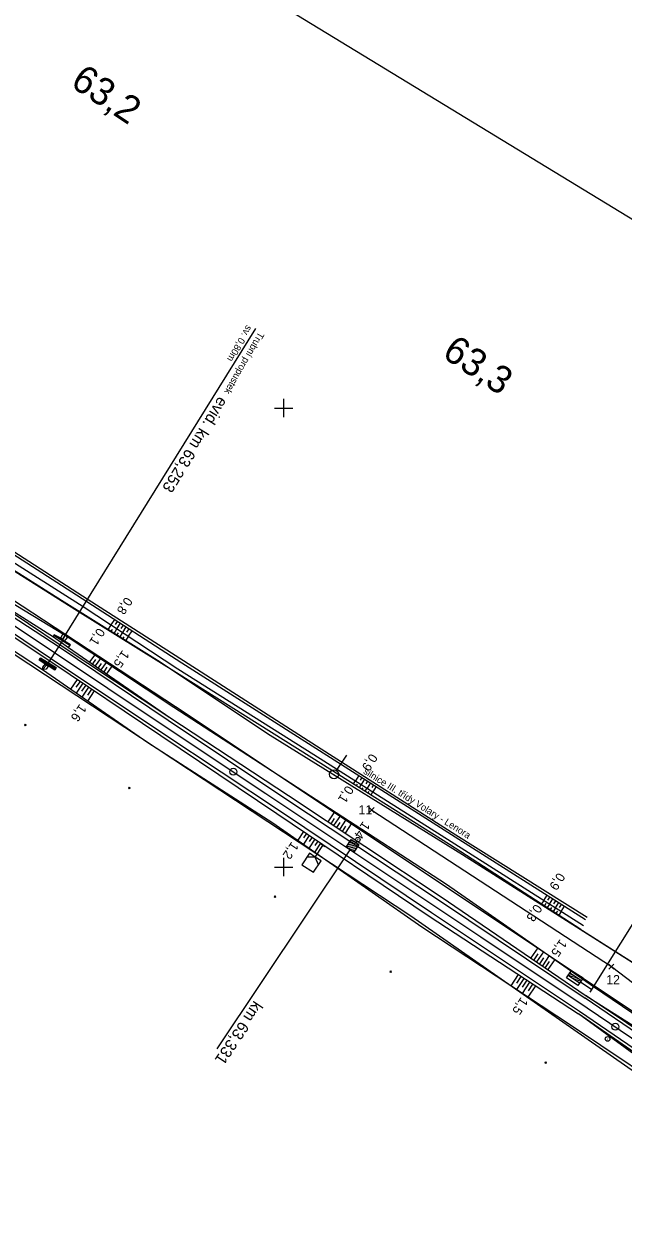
# Model space of a CAD drawing. Extents: x -804899 to -803847, y -1165742 to -1164942.
# Drawn here: x -804356.6 to -804226, y -1165474.6 to -1165216.2 of the extents above; entities that cross this region are included whole.
import ezdxf

# ---------------------------------------------------------------- set-up
doc = ezdxf.new("R2010")
doc.units = 0
for name, color, linetype in [('0381KM061-064P - Vrstva 1', 7, 'Continuous'), ('0381KM061-064P - Vrstva 13', 7, 'Continuous'), ('0381KM061-064P - Vrstva 17', 7, 'Continuous'), ('0381KM061-064P - Vrstva 19', 7, 'Continuous'), ('0381KM061-064P - Vrstva 27', 7, 'Continuous'), ('0381KM061-064P - Vrstva 3', 7, 'Continuous'), ('0381KM061-064P - Vrstva 36', 7, 'Continuous'), ('0381KM061-064P - Vrstva 4', 7, 'Continuous'), ('0381KM061-064P - Vrstva 48', 7, 'Continuous'), ('0381KM061-064P - Vrstva 49', 7, 'Continuous'), ('0381KM061-064P - Vrstva 51', 7, 'Continuous'), ('0381KM061-064P - Vrstva 55', 7, 'Continuous'), ('0381KM061-064P - Vrstva 7', 7, 'Continuous'), ('0381KM061-064P - Vrstva 8', 7, 'Continuous'), ('Default', 7, 'Continuous'), ('formát', 7, 'Continuous'), ('hran DP - hran DP', 7, 'Continuous'), ('krizky_1000 - Vrstva 1', 7, 'Continuous'), ('PSR_C2_3_Lomove_body_Lenora - Vrstva 60', 7, 'Continuous'), ('PSR_C2_3_trasa_Lenora - Kabelová trasa', 7, 'Continuous')]:
    doc.layers.add(name, color=color, linetype=linetype)

msp = doc.modelspace()

# ---------------------------------------------------------------- linework, layer by layer
at = {"layer": '0381KM061-064P - Vrstva 1'}
for points in [[(-804619.36, -1165173.74), (-804594.78, -1165190.05), (-804577, -1165201.91), (-804561.16, -1165212.47), (-804538.32, -1165227.67), (-804515.3, -1165243.02), (-804489.41, -1165260.27), (-804477.81, -1165268), (-804447.6, -1165288.14), (-804422.03, -1165305.2), (-804398.19, -1165321.09), (-804394.23, -1165323.73), (-804371.85, -1165338.65), (-804349.9, -1165353.29), (-804326.64, -1165368.8), (-804303.84, -1165384.01), (-804280.33, -1165399.7), (-804257.04, -1165415.23), (-804233.85, -1165430.69)], [(-804233.85, -1165430.69), (-804221.71, -1165438.86), (-804209.06, -1165447.77)]]:
    msp.add_lwpolyline(points, dxfattribs=at)
at = {"layer": '0381KM061-064P - Vrstva 13'}
for points in [[(-804348.53, -1165350.16), (-804348.11, -1165349.19), (-804347.55, -1165349.48)], [(-804347.71, -1165350.75), (-804347.06, -1165350.02), (-804347.55, -1165349.48)], [(-804351.94, -1165355.72), (-804352.52, -1165356.42), (-804352.55, -1165356.96)], [(-804351.23, -1165356.15), (-804351.73, -1165356.92), (-804352.55, -1165356.96)]]:
    msp.add_lwpolyline(points, dxfattribs=at)
for centre, major_axis, ratio, start_param, end_param in [((-804348.06, -1165350.36), (0.502, -0.373), 0.294364, 3.805363, 5.70381), ((-804351.59, -1165355.94), (-0.372, 0.23), 0.069899, 3.50752, 6.025727)]:
    msp.add_ellipse(centre, major_axis=major_axis, ratio=ratio, start_param=start_param, end_param=end_param, dxfattribs=at)
at = {"layer": '0381KM061-064P - Vrstva 17'}
for points in [[(-804349.85, -1165349.62), (-804346.55, -1165351.67)], [(-804349.69, -1165356.94), (-804352.99, -1165354.74)]]:
    msp.add_lwpolyline(points, dxfattribs=at)
at = {"layer": '0381KM061-064P - Vrstva 19'}
for p, q in [((-804348.23, -1165350.54), (-804306.04, -1165282.63)), ((-804348.12, -1165350.55), (-804351.58, -1165355.92))]:
    msp.add_line(p, q, dxfattribs=at)
for points in [[(-804350.13, -1165349.85), (-804349.96, -1165349.4), (-804349.94, -1165349.53)], [(-804346.52, -1165351.56), (-804349.94, -1165349.53), (-804350.13, -1165349.85), (-804346.84, -1165352.14), (-804346.52, -1165351.56)], [(-804349.96, -1165349.4), (-804348.53, -1165350.16)], [(-804346.41, -1165351.59), (-804347.71, -1165350.75)], [(-804346.84, -1165352.14), (-804346.41, -1165351.59), (-804346.52, -1165351.56)], [(-804353.14, -1165354.84), (-804353.21, -1165354.88), (-804352.95, -1165354.5)], [(-804353.14, -1165354.84), (-804349.82, -1165357.01), (-804349.52, -1165356.59), (-804352.95, -1165354.5), (-804353.14, -1165354.84)], [(-804353.21, -1165354.88), (-804351.94, -1165355.72)], [(-804349.84, -1165357.12), (-804351.23, -1165356.15)], [(-804349.52, -1165356.59), (-804349.84, -1165357.12), (-804349.82, -1165357.01)]]:
    msp.add_lwpolyline(points, dxfattribs=at)
for centre, major_axis, ratio, start_param, end_param in [((-804348.14, -1165350.46), (-0.469, 0.338), 0.066779, 5.748415, 9.878714), ((-804348.06, -1165350.36), (0.502, -0.373), 0.294364, 3.805363, 5.70381), ((-804351.59, -1165355.96), (-0.405, 0.253), 0.126448, 5.826099, 9.990944), ((-804351.59, -1165355.94), (-0.372, 0.23), 0.069899, 3.50752, 6.025727)]:
    msp.add_ellipse(centre, major_axis=major_axis, ratio=ratio, start_param=start_param, end_param=end_param, dxfattribs=at)
at = {"layer": '0381KM061-064P - Vrstva 27'}
msp.add_line((-804283.87, -1165394.04), (-804283.77, -1165394.04), dxfattribs=at)
msp.add_circle((-804283.82, -1165394.04), 0.5, dxfattribs=at)
at = {"layer": '0381KM061-064P - Vrstva 3'}
for p, q in [((-804283.6, -1165395.11), (-804286.38, -1165395.66)), ((-804284.05, -1165394.82), (-804286.08, -1165395.22)), ((-804283.9, -1165395.55), (-804285.94, -1165395.96)), ((-804284.49, -1165394.52), (-804285.79, -1165394.78)), ((-804284.93, -1165394.23), (-804285.5, -1165394.34)), ((-804284.19, -1165395.99), (-804285.5, -1165396.25)), ((-804285.55, -1165396.22), (-804314.54, -1165439.64)), ((-804284.49, -1165396.43), (-804285.06, -1165396.55))]:
    msp.add_line(p, q, dxfattribs=at)
msp.add_lwpolyline([(-804284.72, -1165396.77), (-804286.38, -1165395.66), (-804285.27, -1165394), (-804283.6, -1165395.11)], close=True, dxfattribs=at)
at = {"layer": '0381KM061-064P - Vrstva 36'}
for p, q in [((-804288.43, -1165378.96), (-804286.21, -1165375.63)), ((-804288.99, -1165379.79), (-804288.99, -1165379.79))]:
    msp.add_line(p, q, dxfattribs=at)
msp.add_circle((-804288.99, -1165379.79), 1, dxfattribs=at)
at = {"layer": '0381KM061-064P - Vrstva 4'}
for points in [[(-804755.73, -1165115.93), (-804748.17, -1165116.91), (-804721.25, -1165123.25), (-804698.66, -1165130.22), (-804681.33, -1165136.99), (-804671.47, -1165141.65), (-804648.84, -1165153.36), (-804638.11, -1165160.03), (-804624.48, -1165168.7), (-804602.56, -1165183.07), (-804574.47, -1165201.72), (-804542.72, -1165222.84), (-804507.36, -1165246.55), (-804477.08, -1165266.82), (-804448.75, -1165285.88), (-804421.18, -1165304.15), (-804392.89, -1165323.09), (-804369.85, -1165338.37), (-804348.86, -1165352.04), (-804325.13, -1165367.98), (-804299.32, -1165385.27), (-804266.05, -1165407.31), (-804234.28, -1165428.6)], [(-804755.73, -1165115.93), (-804748.03, -1165116.49), (-804721.05, -1165122.36), (-804698.44, -1165129.77), (-804680.98, -1165136.5), (-804671.21, -1165140.89), (-804648.42, -1165152.46), (-804637.55, -1165159.43), (-804624.04, -1165168.29), (-804602.25, -1165182.38), (-804573.74, -1165201.2), (-804542.46, -1165222.56), (-804507.06, -1165246.03), (-804476.47, -1165266.24), (-804448.31, -1165285.08), (-804421.02, -1165303.1), (-804392.59, -1165322.59), (-804369.41, -1165337.65), (-804348.68, -1165351.59), (-804324.76, -1165367.42), (-804298.9, -1165384.42), (-804265.65, -1165406.5), (-804234.05, -1165428.04)], [(-804626.64, -1165171.43), (-804605.18, -1165186.34), (-804576.91, -1165204.69), (-804544.69, -1165226.09), (-804509.35, -1165249.3), (-804478.87, -1165269.77), (-804450.06, -1165288.98), (-804422.82, -1165307.11), (-804394.42, -1165325.66), (-804371.77, -1165341.24), (-804350.46, -1165355.38), (-804326.73, -1165371.34), (-804301.47, -1165388.34), (-804268.3, -1165410.72), (-804235.74, -1165432.01)], [(-804576.36, -1165204.15), (-804544.19, -1165225.52), (-804508.95, -1165249), (-804478.52, -1165269.18), (-804449.67, -1165288.56), (-804422.62, -1165306.58), (-804394.22, -1165325.33), (-804371.37, -1165340.61), (-804350.54, -1165354.66), (-804326.31, -1165370.81), (-804300.9, -1165387.72), (-804267.8, -1165409.92), (-804235.52, -1165431.44)], [(-804208.29, -1165446.31), (-804234.28, -1165428.6)], [(-804207.68, -1165445.74), (-804234.05, -1165428.04)], [(-804210.55, -1165449.47), (-804235.74, -1165432.01)], [(-804235.52, -1165431.44), (-804210.13, -1165448.78)]]:
    msp.add_lwpolyline(points, dxfattribs=at)
at = {"layer": '0381KM061-064P - Vrstva 48'}
for p, q in [((-804337.56, -1165347.25), (-804336.79, -1165346.06)), ((-804336.62, -1165347.19), (-804336.16, -1165346.47)), ((-804336.3, -1165348.08), (-804335.53, -1165346.88)), ((-804338.21, -1165348.31), (-804337.55, -1165347.26)), ((-804337.57, -1165348.71), (-804337.25, -1165348.19)), ((-804336.93, -1165349.11), (-804336.29, -1165348.08)), ((-804336.3, -1165349.51), (-804335.98, -1165349)), ((-804335.66, -1165349.9), (-804335.04, -1165348.91)), ((-804335.36, -1165348.01), (-804334.9, -1165347.28)), ((-804335.05, -1165348.91), (-804334.27, -1165347.69)), ((-804334.11, -1165348.83), (-804333.64, -1165348.1)), ((-804333.8, -1165349.73), (-804333.01, -1165348.51)), ((-804335.03, -1165350.3), (-804334.72, -1165349.81)), ((-804334.39, -1165350.7), (-804333.79, -1165349.74)), ((-804341.15, -1165353.74), (-804342.25, -1165355.32)), ((-804340.97, -1165354.79), (-804341.63, -1165355.74)), ((-804339.9, -1165354.57), (-804341.01, -1165356.17)), ((-804339.73, -1165355.63), (-804340.4, -1165356.6)), ((-804338.66, -1165355.4), (-804339.78, -1165357.02)), ((-804338.48, -1165356.47), (-804339.16, -1165357.45)), ((-804337.41, -1165356.23), (-804338.55, -1165357.88)), ((-804346.34, -1165361.27), (-804344.9, -1165359.12)), ((-804345.15, -1165360.83), (-804344.27, -1165359.54)), ((-804345.11, -1165362.12), (-804343.65, -1165359.96)), ((-804343.91, -1165361.68), (-804343.03, -1165360.37)), ((-804343.88, -1165362.98), (-804342.41, -1165360.79)), ((-804342.67, -1165362.53), (-804341.79, -1165361.21)), ((-804342.64, -1165363.83), (-804341.16, -1165361.63)), ((-804283.59, -1165380.05), (-804284.34, -1165381.22)), ((-804282.96, -1165380.46), (-804283.33, -1165381.04)), ((-804284.75, -1165381.87), (-804284.34, -1165381.22)), ((-804284.11, -1165382.27), (-804283.91, -1165381.95)), ((-804283.48, -1165382.67), (-804283.07, -1165382.02)), ((-804282.33, -1165380.86), (-804283.07, -1165382.02)), ((-804282.85, -1165383.07), (-804282.64, -1165382.75)), ((-804282.21, -1165383.47), (-804281.81, -1165382.82)), ((-804281.7, -1165381.26), (-804282.07, -1165381.84)), ((-804281.06, -1165381.67), (-804281.8, -1165382.82)), ((-804280.43, -1165382.07), (-804280.8, -1165382.65)), ((-804279.8, -1165382.47), (-804280.54, -1165383.63)), ((-804281.58, -1165383.87), (-804281.37, -1165383.55)), ((-804280.94, -1165384.27), (-804280.54, -1165383.62)), ((-804290.26, -1165390.16), (-804288.8, -1165387.95)), ((-804289.64, -1165390.57), (-804288.9, -1165389.46)), ((-804289.01, -1165390.98), (-804287.54, -1165388.76)), ((-804288.39, -1165391.4), (-804287.65, -1165390.29)), ((-804287.76, -1165391.81), (-804286.28, -1165389.58)), ((-804286.51, -1165392.64), (-804285.02, -1165390.4)), ((-804295.65, -1165392.27), (-804296.91, -1165394.13)), ((-804294.41, -1165393.1), (-804295.68, -1165394.99)), ((-804295.03, -1165392.69), (-804295.66, -1165393.62)), ((-804293.79, -1165393.53), (-804294.43, -1165394.47)), ((-804287.14, -1165392.23), (-804286.4, -1165391.11)), ((-804293.17, -1165393.94), (-804294.45, -1165395.85)), ((-804291.92, -1165394.78), (-804293.22, -1165396.71)), ((-804292.54, -1165394.36), (-804293.19, -1165395.32)), ((-804243.31, -1165407.27), (-804242.59, -1165406.14)), ((-804243.31, -1165407.27), (-804243.8, -1165408.03)), ((-804242.88, -1165407.98), (-804243.17, -1165408.43)), ((-804242.05, -1165408.07), (-804242.54, -1165408.84)), ((-804242.39, -1165407.22), (-804241.96, -1165406.54)), ((-804242.05, -1165408.07), (-804241.33, -1165406.94)), ((-804241.61, -1165408.79), (-804241.91, -1165409.25)), ((-804240.78, -1165408.88), (-804241.29, -1165409.66)), ((-804241.13, -1165408.02), (-804240.69, -1165407.34)), ((-804240.78, -1165408.88), (-804240.06, -1165407.74)), ((-804239.86, -1165408.83), (-804239.43, -1165408.15)), ((-804239.52, -1165409.69), (-804238.8, -1165408.55)), ((-804240.35, -1165409.6), (-804240.66, -1165410.06)), ((-804239.52, -1165409.69), (-804240.03, -1165410.47)), ((-804244.59, -1165417.6), (-804246.1, -1165419.82)), ((-804244.58, -1165418.91), (-804245.48, -1165420.24)), ((-804243.36, -1165418.45), (-804244.86, -1165420.66)), ((-804242.13, -1165419.31), (-804243.62, -1165421.51)), ((-804243.34, -1165419.76), (-804244.24, -1165421.09)), ((-804242.11, -1165420.61), (-804243.01, -1165421.93)), ((-804240.9, -1165420.17), (-804242.39, -1165422.35)), ((-804250.43, -1165425.88), (-804248.84, -1165423.45)), ((-804249.18, -1165426.71), (-804247.58, -1165424.27)), ((-804249.17, -1165425.32), (-804248.21, -1165423.85)), ((-804247.93, -1165427.54), (-804246.33, -1165425.09)), ((-804247.91, -1165426.15), (-804246.95, -1165424.68)), ((-804246.68, -1165428.37), (-804245.07, -1165425.91)), ((-804246.66, -1165426.97), (-804245.7, -1165425.5))]:
    msp.add_line(p, q, dxfattribs=at)
at = {"layer": '0381KM061-064P - Vrstva 49'}
for p, q in [((-804356.09, -1165369.23), (-804356.44, -1165368.87)), ((-804356.09, -1165368.87), (-804356.44, -1165369.23)), ((-804333.45, -1165382.97), (-804333.81, -1165382.62)), ((-804333.45, -1165382.62), (-804333.81, -1165382.97)), ((-804301.7, -1165406.66), (-804302.06, -1165406.31)), ((-804301.7, -1165406.31), (-804302.06, -1165406.66)), ((-804276.5, -1165422.97), (-804276.85, -1165422.62)), ((-804276.5, -1165422.62), (-804276.85, -1165422.97)), ((-804242.71, -1165442.85), (-804243.07, -1165442.5)), ((-804242.71, -1165442.5), (-804243.07, -1165442.85))]:
    msp.add_line(p, q, dxfattribs=at)
for points in [[(-804668.09, -1165135.13), (-804646.08, -1165148.91), (-804635.34, -1165155.79), (-804621.98, -1165164.4), (-804599.68, -1165178.86), (-804570.23, -1165197.63), (-804539.04, -1165217.4), (-804503.79, -1165239.32), (-804473.21, -1165259.25), (-804445.02, -1165277.37), (-804416.3, -1165295.6), (-804385.23, -1165314.87), (-804342.84, -1165342.16), (-804322.16, -1165355.5), (-804292.15, -1165374.6), (-804262.58, -1165393.44), (-804234.25, -1165411.43)], [(-804668.53, -1165136.56), (-804646.51, -1165150.38), (-804635.75, -1165157.19), (-804622.88, -1165165.28), (-804600.74, -1165180), (-804571.06, -1165199.05), (-804539.91, -1165219.23), (-804504.85, -1165241.38), (-804474.07, -1165260.59), (-804445.75, -1165278.86), (-804417.38, -1165297.08), (-804386.13, -1165316.29), (-804343.68, -1165343.22), (-804323.05, -1165356.81), (-804293.41, -1165375.48), (-804263.45, -1165394.43), (-804234.68, -1165412.78)], [(-804576.91, -1165204.69), (-804544.69, -1165226.09), (-804509.35, -1165249.3), (-804478.87, -1165269.77), (-804450.06, -1165288.98), (-804422.82, -1165307.11), (-804394.42, -1165325.66), (-804371.77, -1165341.24), (-804350.46, -1165355.38), (-804326.73, -1165371.34), (-804301.47, -1165388.34), (-804268.3, -1165410.72), (-804235.74, -1165432.01)], [(-804474.97, -1165261.14), (-804446.16, -1165279.93), (-804417.55, -1165297.62), (-804371.56, -1165327.37), (-804344.89, -1165344.14), (-804323.3, -1165357.63), (-804293.83, -1165376.15), (-804263.84, -1165395.04), (-804235.23, -1165413.58)], [(-804475.98, -1165263.3), (-804448.01, -1165281.64), (-804419.88, -1165300.43), (-804390.2, -1165320.54), (-804368.79, -1165336.61), (-804347.55, -1165349.48), (-804323.92, -1165365.2), (-804298.45, -1165381.67), (-804264.49, -1165403.75), (-804232.5, -1165426.01)], [(-804424.02, -1165310.32), (-804397.08, -1165327.6), (-804372.3, -1165344.03), (-804352.55, -1165356.96), (-804329.59, -1165372.88)], [(-804369.41, -1165337.65), (-804350.13, -1165349.85)], [(-804348.53, -1165350.16), (-804349.96, -1165349.4), (-804350.13, -1165349.85)], [(-804348.12, -1165350.55), (-804347.55, -1165349.48)], [(-804346.84, -1165352.14), (-804346.41, -1165351.59), (-804347.71, -1165350.75)], [(-804346.84, -1165352.14), (-804324.76, -1165367.42)], [(-804351.94, -1165355.72), (-804353.21, -1165354.88), (-804352.95, -1165354.5), (-804349.52, -1165356.59), (-804349.84, -1165357.12), (-804351.23, -1165356.15)], [(-804351.58, -1165355.92), (-804352.55, -1165356.96)], [(-804324.76, -1165367.42), (-804298.9, -1165384.42), (-804265.65, -1165406.5), (-804234.05, -1165428.04)], [(-804329.59, -1165372.88), (-804302.32, -1165390.35), (-804269.85, -1165413.05), (-804237.3, -1165434.57)], [(-804232.5, -1165426.01), (-804205.4, -1165444.42), (-804185.08, -1165460.87), (-804164.82, -1165478.77), (-804146.89, -1165498.25)], [(-804234.05, -1165428.04), (-804207.28, -1165445), (-804187.24, -1165461.29), (-804165.68, -1165480.42), (-804149.47, -1165498.06), (-804149.78, -1165499.19)], [(-804211.12, -1165449.96), (-804235.74, -1165432.01)], [(-804237.3, -1165434.57), (-804211.51, -1165451.84), (-804192.43, -1165466.88), (-804171.52, -1165486.4), (-804154.9, -1165505.76)]]:
    msp.add_lwpolyline(points, dxfattribs=at)
for centre, major_axis, ratio, start_param, end_param in [((-804348.06, -1165350.36), (0.502, -0.373), 0.294364, 3.805363, 5.70381), ((-804351.59, -1165355.94), (-0.372, 0.23), 0.069899, 3.50752, 6.025727)]:
    msp.add_ellipse(centre, major_axis=major_axis, ratio=ratio, start_param=start_param, end_param=end_param, dxfattribs=at)
at = {"layer": '0381KM061-064P - Vrstva 51'}
msp.add_line((-804262.45, -1165392.96), (-804233.82, -1165410.93), dxfattribs=at)
msp.add_lwpolyline([(-804728.9, -1165105.9), (-804711.54, -1165108.67), (-804704.35, -1165111.8), (-804683.69, -1165124.09), (-804676.95, -1165128.43), (-804667.36, -1165134.41), (-804645.71, -1165148.3), (-804634.7, -1165155.23), (-804621.63, -1165163.62), (-804599.19, -1165178.23), (-804569.67, -1165197.16), (-804538.42, -1165216.77), (-804503.41, -1165238.94), (-804472.82, -1165258.55), (-804444.57, -1165276.4), (-804415.82, -1165294.73), (-804384.7, -1165314.57), (-804342.59, -1165341.72), (-804321.8, -1165355.02), (-804291.77, -1165374.22), (-804262.45, -1165392.96)], dxfattribs=at)
at = {"layer": '0381KM061-064P - Vrstva 55'}
msp.add_lwpolyline([(-804468.27, -1165264.32), (-804426.86, -1165291.43), (-804390.35, -1165315.35), (-804348.41, -1165341.86), (-804327.45, -1165354.94), (-804302.94, -1165371.26), (-804261.01, -1165397.26), (-804213.5, -1165427.44), (-804191.69, -1165441.88), (-804177.28, -1165451.4), (-804169.73, -1165458.18), (-804172.29, -1165470.42), (-804193.11, -1165453.43), (-804217.51, -1165435.77), (-804323.51, -1165365.07), (-804402.46, -1165313.29)], close=True, dxfattribs=at)
at = {"layer": '0381KM061-064P - Vrstva 7'}
for p, q in [((-804293.09, -1165397.82), (-804291.43, -1165395.33)), ((-804291.01, -1165395.61), (-804291.84, -1165395.05)), ((-804229.44, -1165437.43), (-804229.36, -1165437.49))]:
    msp.add_line(p, q, dxfattribs=at)
for points in [[(-804293.09, -1165397.82), (-804294.34, -1165396.99), (-804296, -1165399.49), (-804293.51, -1165401.15), (-804291.84, -1165398.66), (-804293.09, -1165397.82)], [(-804292.4, -1165399.49), (-804293.09, -1165397.82), (-804294.9, -1165397.82)]]:
    msp.add_lwpolyline(points, dxfattribs=at)
for centre, radius in [((-804310.94, -1165379.23), 0.75), ((-804227.7, -1165434.8), 0.75), ((-804229.4, -1165437.46), 0.5)]:
    msp.add_circle(centre, radius, dxfattribs=at)
at = {"layer": '0381KM061-064P - Vrstva 8'}
for p, q in [((-804232.81, -1165426.68), (-804194.18, -1165364.63)), ((-804236.98, -1165423.48), (-804237.94, -1165423.67)), ((-804237.42, -1165423.18), (-804237.73, -1165423.24)), ((-804236.54, -1165423.77), (-804237.5, -1165423.96)), ((-804236.09, -1165424.06), (-804237.06, -1165424.26)), ((-804235.65, -1165424.36), (-804236.62, -1165424.55)), ((-804235.21, -1165424.65), (-804236.18, -1165424.85)), ((-804235.33, -1165425.06), (-804235.74, -1165425.14)), ((-804233.22, -1165427.3), (-804232.39, -1165426.05))]:
    msp.add_line(p, q, dxfattribs=at)
for points in [[(-804235.86, -1165425.84), (-804238.35, -1165424.18), (-804237.24, -1165422.52), (-804234.75, -1165424.18), (-804235.86, -1165425.84)], [(-804235.3, -1165425.01), (-804232.81, -1165426.68)]]:
    msp.add_lwpolyline(points, dxfattribs=at)
msp.add_lwpolyline([(-804235.5, -1165425.3), (-804237.99, -1165423.64), (-804237.61, -1165423.06), (-804235.11, -1165424.72)], close=True, dxfattribs=at)
at = {"layer": 'formát'}
msp.add_line((-804206.05, -1165269.84), (-804743.98, -1164941.92), dxfattribs=at)
at = {"layer": 'hran DP - hran DP'}
for p, q in [((-804390.35, -1165315.35), (-804348.41, -1165341.86)), ((-804272.3, -1165410.7), (-804413.53, -1165317.49)), ((-804348.41, -1165341.86), (-804327.45, -1165354.94)), ((-804327.45, -1165354.94), (-804302.94, -1165371.26)), ((-804302.94, -1165371.26), (-804261.01, -1165397.26)), ((-804261.01, -1165397.26), (-804213.5, -1165427.44)), ((-804199.72, -1165461.33), (-804272.3, -1165410.7))]:
    msp.add_line(p, q, dxfattribs=at)
at = {"layer": 'krizky_1000 - Vrstva 1'}
for points in [[(-804302, -1165300), (-804298, -1165300)], [(-804300, -1165298), (-804300, -1165302)], [(-804300, -1165398), (-804300, -1165402)], [(-804302, -1165400), (-804298, -1165400)]]:
    msp.add_lwpolyline(points, dxfattribs=at)
at = {"layer": 'PSR_C2_3_Lomove_body_Lenora - Vrstva 60'}
for p, q in [((-804281.33, -1165388.13), (-804280.23, -1165387.03)), ((-804280.23, -1165388.13), (-804281.33, -1165387.03)), ((-804229.12, -1165422.24), (-804228.02, -1165421.14)), ((-804228.02, -1165422.24), (-804229.12, -1165421.14))]:
    msp.add_line(p, q, dxfattribs=at)
at = {"layer": 'PSR_C2_3_trasa_Lenora - Kabelová trasa'}
msp.add_lwpolyline([(-804280.78, -1165387.58), (-804228.57, -1165421.69), (-804204.49, -1165439.97), (-804181.72, -1165458.66)], dxfattribs=at)

# ---------------------------------------------------------------- texts
at = {"layer": '0381KM061-064P - Vrstva 19'}
for s, height, rotation, p in [('sv. 0,80m', 1.5, 240.1321, (-804308.03, -1165281.79)), ('Trubní propustek', 1.5, 240.1321, (-804305.42, -1165283.29)), ('evid. km 63,253', 2.5, 238.1402, (-804314.07, -1165297.33))]:
    msp.add_text(s, height=height, rotation=rotation, dxfattribs=at).set_placement(p)
at = {"layer": '0381KM061-064P - Vrstva 3'}
msp.add_text('km 63,331', height=2.5, rotation=236.2785, dxfattribs=at).set_placement((-804306.42, -1165428.98))
at = {"layer": '0381KM061-064P - Vrstva 48'}
for s, rotation, p in [('0,8', 237.1733, (-804334.42, -1165341.01)), ('0,1', 238.0111, (-804340.44, -1165347.75)), ('1,5', 235.3116, (-804335.06, -1165352.61)), ('1,6', 236.0582, (-804344.4, -1165364.35)), ('0,9', 237.503, (-804281.05, -1165375.12)), ('0,1', 237.7998, (-804286.25, -1165382.09)), ('1,4', 236.4166, (-804282.66, -1165389.9)), ('1,2', 236.0013, (-804298.21, -1165394.34)), ('0,9', 237.5753, (-804240.19, -1165401.08)), ('0,3', 237.0482, (-804245.18, -1165407.93)), ('1,5', 235.7229, (-804239.75, -1165415.6)), ('1,5', 236.8157, (-804248.25, -1165428.23))]:
    msp.add_text(s, height=2, rotation=rotation, dxfattribs=at).set_placement(p)
at = {"layer": '0381KM061-064P - Vrstva 51'}
msp.add_text('silnice III. třídy Volary - Lenora', height=1.5, rotation=327.9008, dxfattribs=at).set_placement((-804282.76, -1165379.52))
at = {"layer": '0381KM061-064P - Vrstva 7'}
for s, rotation, p in [('63,2', 326.3093, (-804346.68, -1165229.73)), ('63,3', 326.3024, (-804265.71, -1165288.72))]:
    msp.add_text(s, height=6, rotation=rotation, dxfattribs=at).set_placement(p)
at = {"layer": 'Default'}
for s, p in [('11', (-804283.67, -1165388.55)), ('12', (-804229.69, -1165425.55))]:
    msp.add_text(s, height=2, dxfattribs=at).set_placement(p)

doc.saveas('drawing.dxf')
